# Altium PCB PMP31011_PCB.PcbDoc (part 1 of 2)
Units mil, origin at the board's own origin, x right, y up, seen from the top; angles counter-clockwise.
Board outline 3287.4 x 3750 mil, 4 copper layers (Top Layer, GND, Signal Layer, Bottom Layer), stack 84.834 mil thick; 100 components, 44 nets, 235 pads, 404 vias.
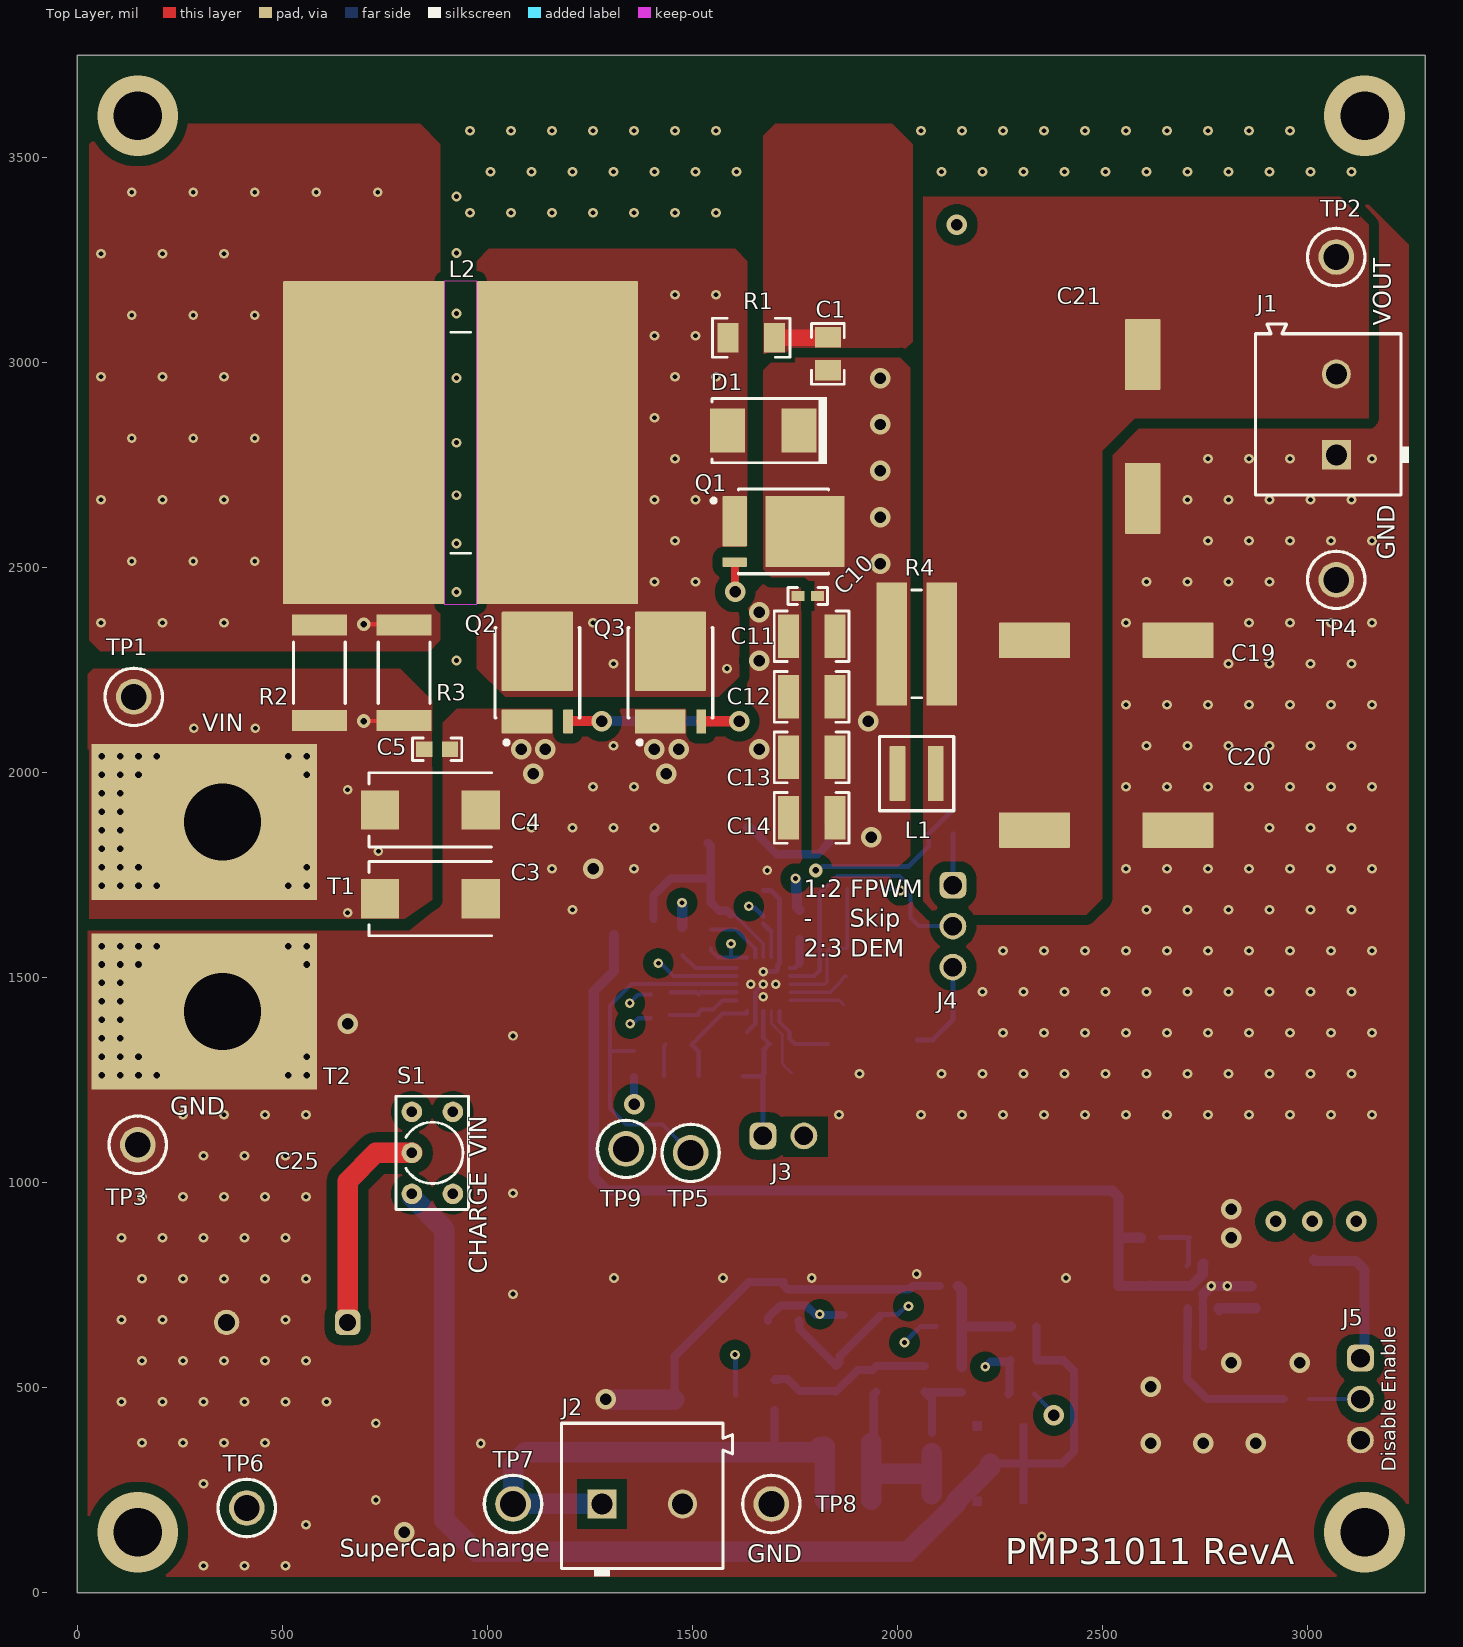
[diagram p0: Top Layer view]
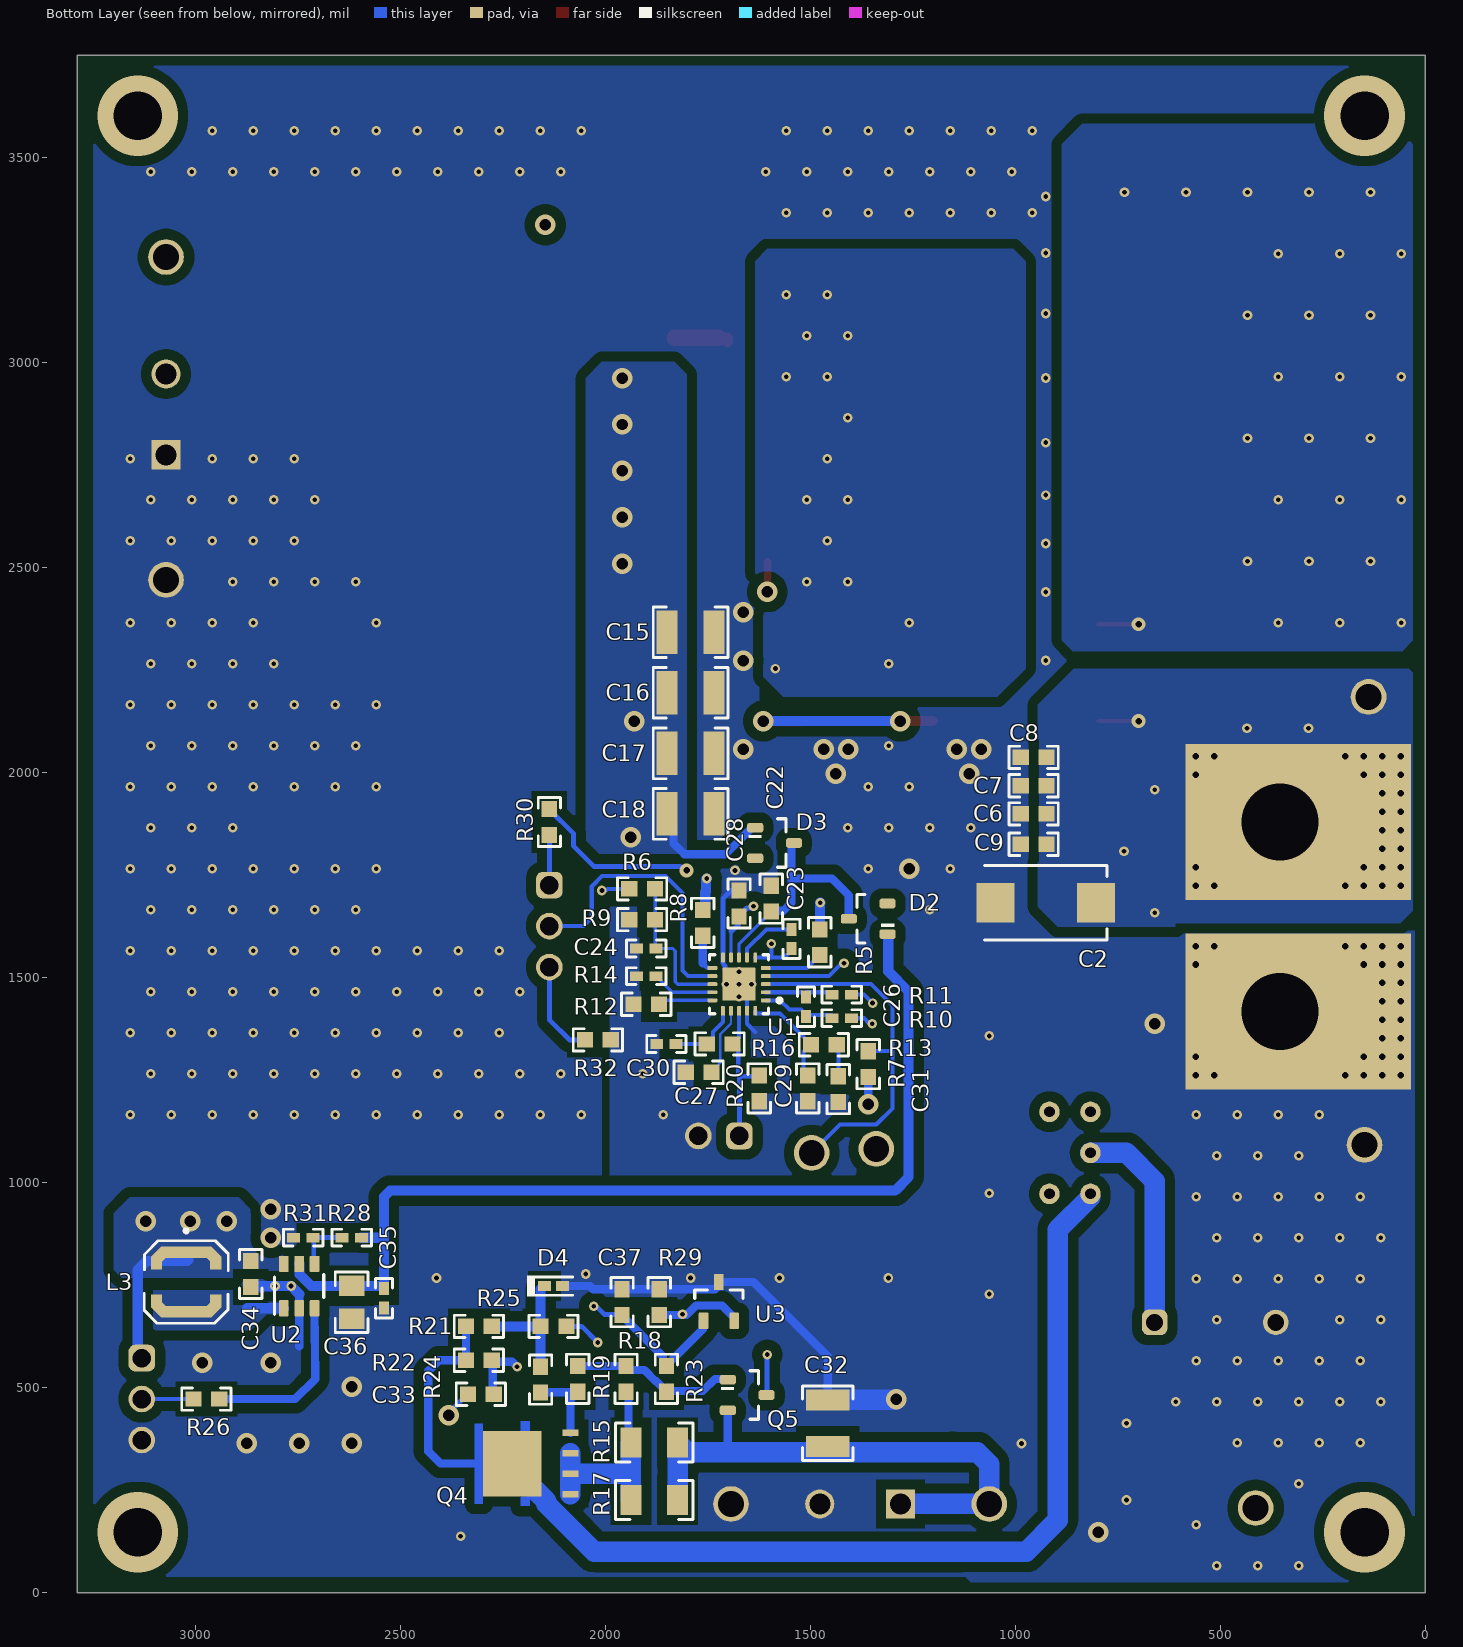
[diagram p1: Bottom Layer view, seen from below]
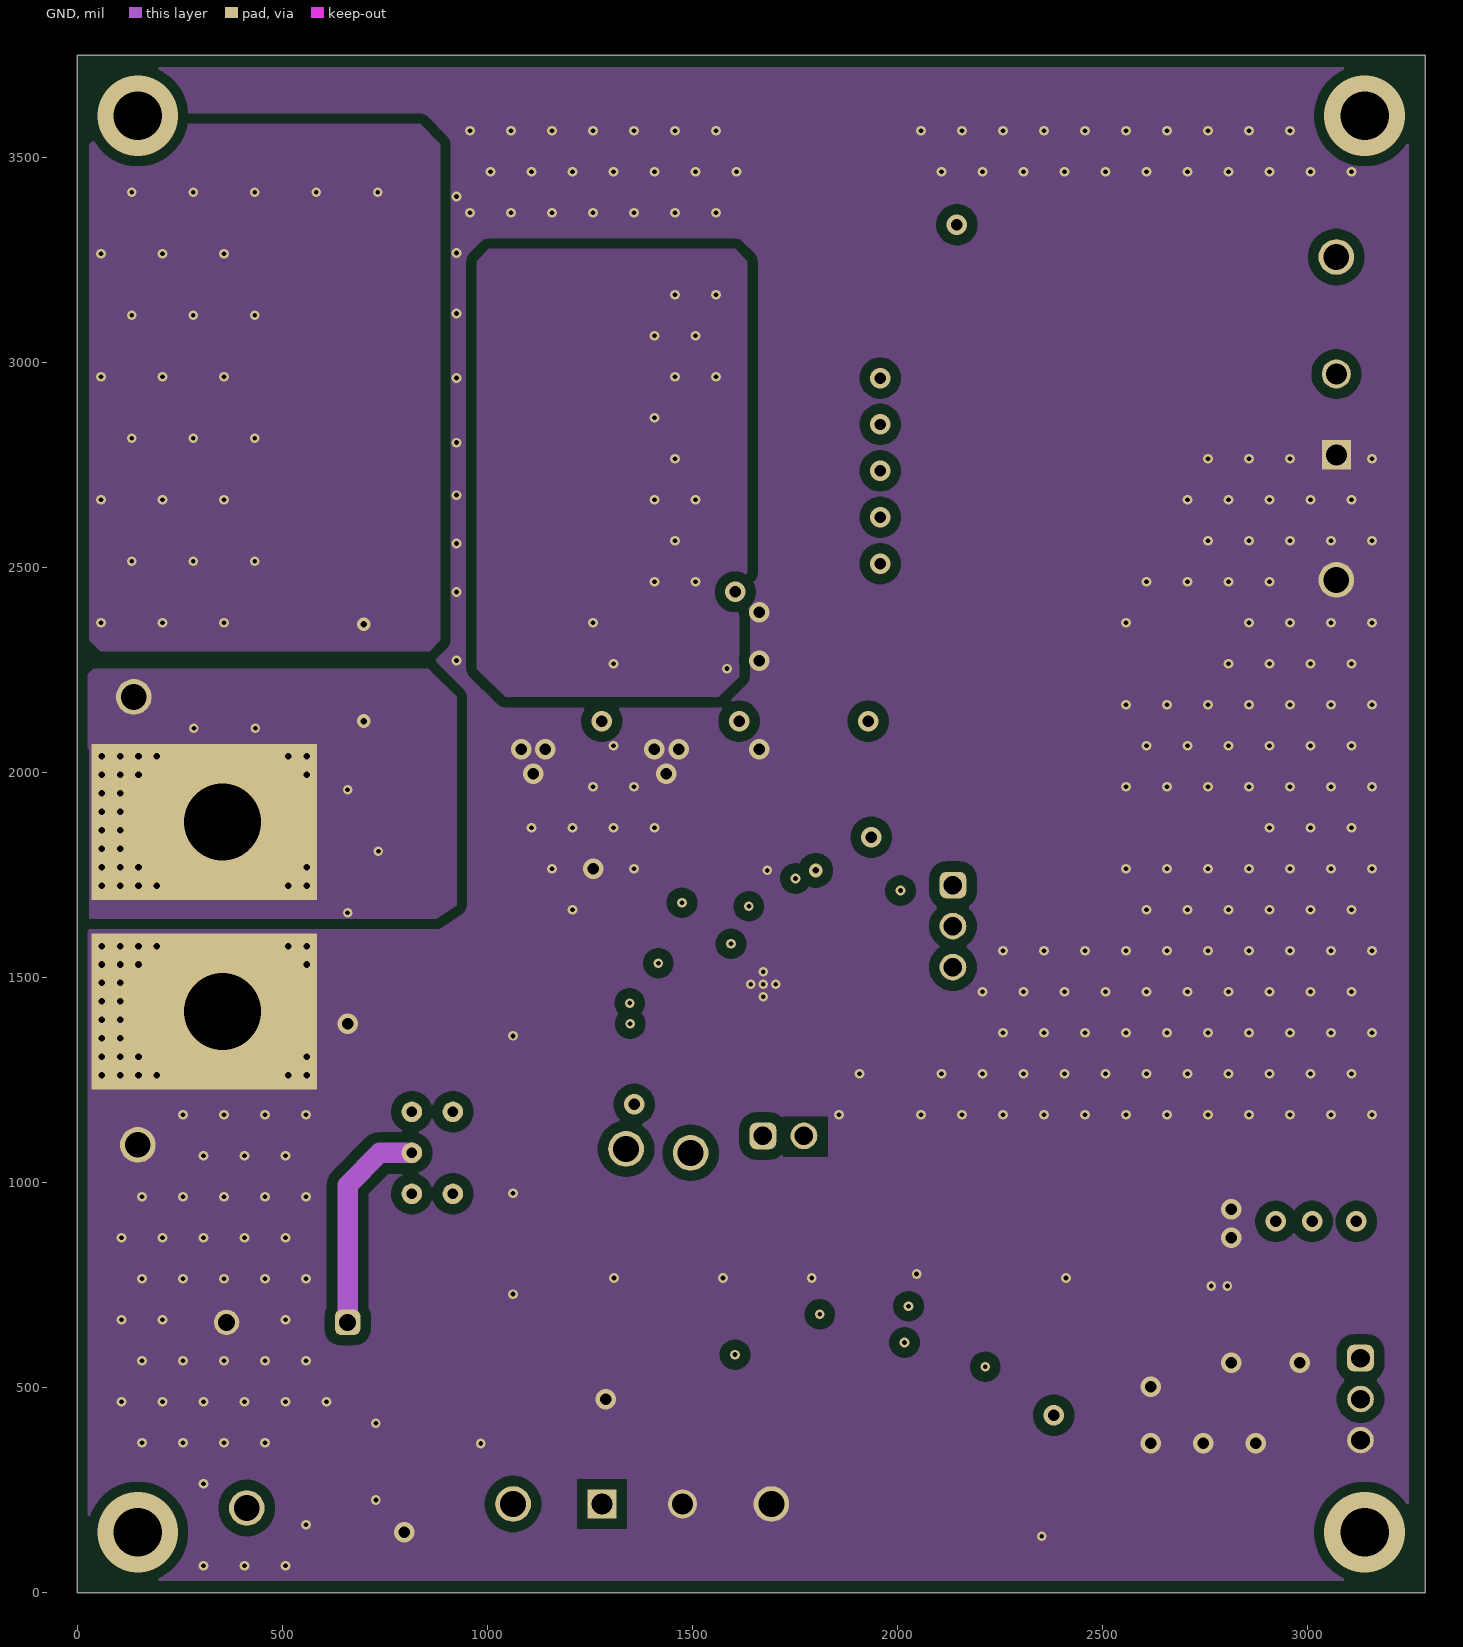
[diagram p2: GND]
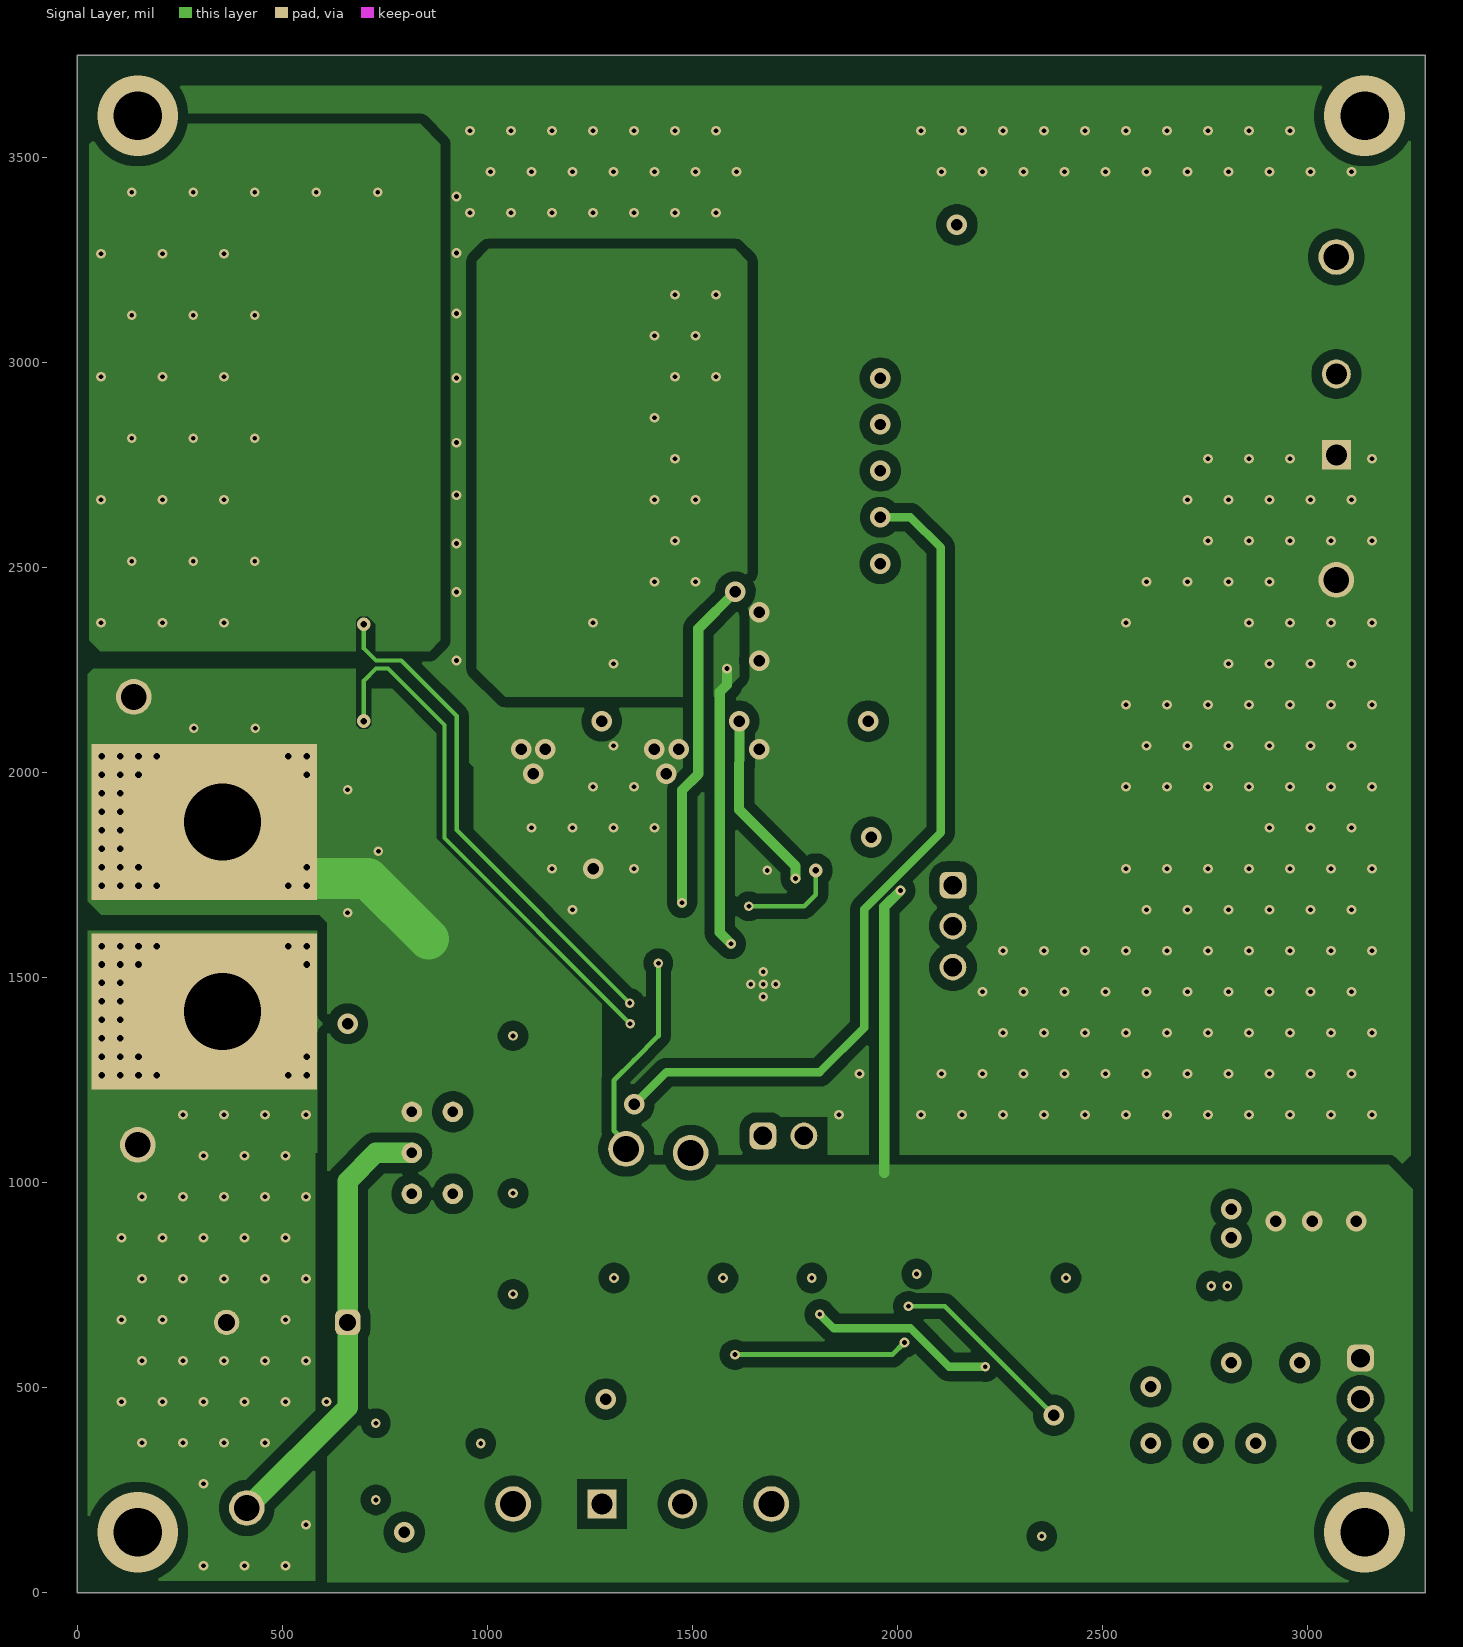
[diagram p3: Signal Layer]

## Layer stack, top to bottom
Top Solder: solder mask 0.4, Solder Resist, Dk 3.5
Top Layer: signal copper 1.4
Dielectric 2: dielectric 10, Dk 4.2
GND: signal copper 1.417
Dielectric1: core 59.2, FR-4, Dk 4.8
Signal Layer: signal copper 1.417
Dielectric 3: dielectric 10, Dk 4.2
Bottom Layer: signal copper 1.4
Bottom Solder: solder mask 0.4, Solder Resist, Dk 3.5

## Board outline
0,0 3287.4,0 3287.4,3750 0,3750

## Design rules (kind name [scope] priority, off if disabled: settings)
AcuteAngle [All] p1: minimum=4.50000000000000E+0001 checktracksonly=FALSE
AssemblyTestPointUsage [All] p1: valid=2
BoardOutlineClearance BoardOutlineClearance_MountingHoles [OnCopper and InComponentClass('Mounting Holes')] p1: gap=39.37 ignorepadtopadclearanceinfootprint=FALSE
BoardOutlineClearance BoardOutlineClearance_Poly [OnCopper and IsPoly] p2: gap=25 ignorepadtopadclearanceinfootprint=FALSE
BoardOutlineClearance [OnCopper and Not InComponentClass('Logo') and not InComponentClass('FiducialMark') and not InRegion(1000,500,4000,800) and not InPoly] p3: gap=75 ignorepadtopadclearanceinfootprint=FALSE
Clearance Clearance_Keepouts [((IsTrack Or IsArc) And Not InPoly) And IsFree and IsKeepOut vs ((IsTrack Or IsArc) And Not InPoly) And IsFree and IsKeepOut] p1: gap=0 ignorepadtopadclearanceinfootprint=FALSE
Clearance Clearance_Poly [InPolygon] p2: gap=25 ignorepadtopadclearanceinfootprint=TRUE
Clearance Clearance_FiducialMark [IsKeepOut and InComponentClass('FiducialMark') vs IsPad and InComponentClass('FiducialMark')] p3: gap=0 ignorepadtopadclearanceinfootprint=FALSE
Clearance [All] p4: gap=7.87 ignorepadtopadclearanceinfootprint=TRUE
ComponentClearance ComponentClearance_MountingHoles_FiducialMarks [InComponentClass('Mounting Holes') vs InComponentClass('FiducialMark')] p1: gap=50 collisioncheckmode=3 verticalgap=10 showdistances=FALSE
ComponentClearance ComponentClearance_Shunt [InComponentClass('Header') vs InComponentClass('Shunt')] p2: gap=0 collisioncheckmode=3 verticalgap=0 showdistances=FALSE
ComponentClearance ComponentClearance_Logo [InComponentClass('Logo')] p3: gap=50 collisioncheckmode=3 verticalgap=10 showdistances=FALSE
ComponentClearance ComponentClearance_ScrewToNut [(HasFootprint('NY PMS 440 0025 PH')) vs (HasFootprint('Keystone_1902C'))] p4: gap=5 collisioncheckmode=3 verticalgap=10 showdistances=FALSE
ComponentClearance ComponentClearance_MountingHoles [InComponentClass('Mounting Holes')] p5: gap=250 collisioncheckmode=3 verticalgap=100000 showdistances=FALSE
ComponentClearance ComponentClearance_SmallPassives [HasFootprint('0201*') or HasFootprint('0402*') or HasFootprint('0508') or HasFootprint('0603*') or HasFootprint('0612') or HasFootprint('0805*') or HasFootprint('0815*') or HasFootprint('0830*') or HasFootprint('1206*') or HasFootprint('1210*') or HasFootprint('1808*') or HasFootprint('1812*') or HasFootprint('1825*') or HasFootprint('2010*') or HasFootprint('2220*') or HasFootprint('2225*') or HasFootprint('2512*') or HasFootprint('2728*') or HasFootprint('3518*') vs HasFootprint('0201*') or HasFootprint('0402*') or HasFootprint('0508') or HasFootprint('0603*') or HasFootprint('0612') or HasFootprint('0805*') or HasFootprint('0815*') or HasFootprint('0830*') or HasFootprint('1206*') or HasFootprint('1210*') or HasFootprint('1808*') or HasFootprint('1812*') or HasFootprint('1825*') or HasFootprint('2010*') or HasFootprint('2220*') or HasFootprint('2225*') or HasFootprint('2512*') or HasFootprint('2728*') or HasFootprint('3518*')] p6: gap=14.96 collisioncheckmode=3 verticalgap=10 showdistances=FALSE
ComponentClearance ComponentClearance_THtoSMT [IsThruComponent vs IsSMTComponent] p7: gap=40 collisioncheckmode=3 verticalgap=30 showdistances=FALSE
ComponentClearance ComponentClearance_THtoTH [IsThruComponent vs IsThruComponent] p8: gap=30 collisioncheckmode=3 verticalgap=30 showdistances=FALSE
ComponentClearance [All] p9: gap=30 collisioncheckmode=3 verticalgap=10 showdistances=FALSE
DiffPairsRouting [All] p1: maxlimit=100 minlimit=10 mostfreqgap=10 toplayer_minwidth=15 toplayer_maxwidth=15 toplayer_prefwidth=15 midlayer1_minwidth=15 midlayer1_maxwidth=15 midlayer1_prefwidth=15 midlayer2_minwidth=15 midlayer2_maxwidth=15 midlayer2_prefwidth=15 bottomlayer_minwidth=15 bottomlayer_maxwidth=15 bottomlayer_prefwidth=15 maxuncoupledlength=1000
FabricationTestPointUsage TestPointUsage [All] p1: valid=2 allowmultiple=FALSE
FabricationTestpoint Testpoint [All] p1: side=3 testpointundercomponent=TRUE minsize=40 maxsize=100 preferedsize=60 minholesize=0 maxholesize=40 preferedholesize=32 testpointgrid=1 allowsidetop=TRUE allowsidebottom=TRUE usegrid=TRUE gridtolerance=0.01
FanoutControl Fanout_LCC [IsLCC] p1: bgadir=Out bgaviamode=Centered fanoutstyle=Auto fanoutdirection=Alternating viagrid=1 // Fanout_LCC (Default Rule)
FanoutControl Fanout_BGA [IsBGA] p2: bgadir=Out bgaviamode=Centered fanoutstyle=Auto fanoutdirection=Alternating viagrid=1 // Fanout_BGA (Default Rule)
FanoutControl Fanout_Default [All] p4: bgadir=Out bgaviamode=Centered fanoutstyle=Auto fanoutdirection=Alternating viagrid=1 // Fanout_Default (Default Rule)
FanoutControl Fanout_Small [(CompPinCount < 5)] p5: bgadir=Out bgaviamode=Centered fanoutstyle=Auto fanoutdirection=OutThenIn viagrid=1 // Fanout_Small (Default Rule)
HoleSize [All] p1: absolutevalues=TRUE maxlimit=251 minlimit=7.87 maxpercent=80.000 minpercent=20.000
MinimumAnnularRing MinimumAnnularRing_ThermalPadVias [IsVia and InAnyComponent] p1: minimumring=5.91
MinimumAnnularRing [All] p2: minimumring=5.91
MinimumSolderMaskSliver MinimumSolderMaskSliver_Logo [InComponentClass('Logo') vs InComponentClass('Logo')] p1: minsoldermaskwidth=0.7
MinimumSolderMaskSliver [All] p2: minsoldermaskwidth=3.94
PlaneConnect [All] p1: planeconnectstyle=Direct reliefexpansion=10 reliefentries=4 reliefconductorwidth=10 reliefairgap=10
PolygonConnect PolygonConnect_1 [All vs IsNamedPolygon('TOP_LAYER_NETD1_1_P000')] p1: connectstyle=Direct reliefconductorwidth=10 reliefentries=4 polygonreliefangle="90 Angle" airgapwidth=10
PolygonConnect [All] p2: connectstyle=Direct reliefconductorwidth=10 reliefentries=4 polygonreliefangle="90 Angle" airgapwidth=10
RoutingVias ThermalPadVias [IsVia and InAnyComponent] p1: holewidth=7.87 width=19.68 viastyle="Through Hole" minholewidth=7.87 minwidth=19.68 maxholewidth=12.99 maxwidth=23.62
RoutingVias [All] p2: holewidth=16 width=34 viastyle="Through Hole" minholewidth=11.81 minwidth=23.62 maxholewidth=40 maxwidth=65
SilkToBoardRegionClearance [Not ((IsComment or IsDesignator) And (Hide <> 'False')) and not InRegion(1000,500,4000,800)] p1:
SilkToSilkClearance SilkToSilkClearance_Pb-FreeLogo [(HasFootprint('Pb-Free_Overlay_Medium') OR HasFootprint('Pb-Free_Overlay_Small')) vs (HasFootprint('Pb-Free_Overlay_Medium') OR HasFootprint('Pb-Free_Overlay_Small'))] p1: silktosilkclearance=0
SilkToSilkClearance [All] p2: silktosilkclearance=3.94
SilkToSolderMaskClearance SilkToComponentPadClearance [(IsPad or IsFill or IsRegion) and InAnycomponent] p1: minsilkscreentomaskgap=5 clearancetoexposedcopper=TRUE
SilkToSolderMaskClearance "Silk to Solder Mask Opening" [All] p2: minsilkscreentomaskgap=3.94 clearancetoexposedcopper=FALSE
SolderMaskExpansion [All] p1: expansion=1.97 istentingtop=FALSE
UnRoutedNet [All] p1: checkbadconnections=TRUE
Width [All] p1: maxlimit=100 minlimit=6 preferedwidth=10 checkconnectedcopper=TRUE
14 further rules are at their usual default settings.

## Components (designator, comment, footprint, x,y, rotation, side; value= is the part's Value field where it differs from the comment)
C1 "GRM21BR72A153MA01L" 0805_HV 1830.71,3021.65 r90 top value=0.015uF
C2 "EEFSX0G221ER" 7343-20 925.2,1683.07 r0 bottom value=220uF
C3 "EEFSX0G221ER" 7343-20 861.02,1692.91 r0 top value=220uF
C4 "EEFSX0G221ER" 7343-20 861.02,1909.45 r0 top value=220uF
C5 "GRM188Z71A106MA73D" 0603 877.95,2057.09 r0 top value=10uF
C6 "GRM188Z71A106MA73D" 0603 954.72,1899.61 r0 bottom value=10uF
C7 "GRM188Z71A106MA73D" 0603 954.72,1968.5 r0 bottom value=10uF
C8 "GRM188Z71A106MA73D" 0603 954.72,2037.4 r0 bottom value=10uF
C9 "GRM188Z71A106MA73D" 0603 954.72,1825.79 r0 bottom value=10uF
C10 "GRM155R71C104JA88D" 0402 1781.5,2431.1 r180 top value=0.1uF
C11 "GRM32ER71E226KE15L" 1210_270 1791.34,2332.68 r180 top value=22uF
C12 "GRM32ER71E226KE15L" 1210_270 1791.34,2185.04 r180 top value=22uF
C13 "GRM32ER71E226KE15L" 1210_270 1791.34,2037.4 r180 top value=22uF
C14 "GRM32ER71E226KE15L" 1210_270 1791.34,1889.76 r180 top value=22uF
C15 "GRM32ER71E226KE15L" 1210_270 1791.34,2342.52 r180 bottom value=22uF
C16 "GRM32ER71E226KE15L" 1210_270 1791.34,2194.88 r180 bottom value=22uF
C17 "GRM32ER71E226KE15L" 1210_270 1791.34,2047.24 r180 bottom value=22uF
C18 "GRM32ER71E226KE15L" 1210_270 1791.34,1899.61 r180 bottom value=22uF
C19 "HHXB160ARA471MJA0G" FP-HHXB160ARA471MJA0G_RADIAL-MFG 2509.84,2322.83 r180 top
C20 "HHXB160ARA471MJA0G" FP-HHXB160ARA471MJA0G_RADIAL-MFG 2509.84,1860.24 r180 top
C21 "HHXB160ARA471MJA0G" FP-HHXB160ARA471MJA0G_RADIAL-MFG 2598.43,2844.49 r90 top
C22 "GRM188R71E105KA12D" 0603 1594.49,1692.91 r90 bottom value=1uF
C23 "GRM155R71H104ME14D" 0402 1545.28,1594.54 r270 bottom value=0.1uF
C24 "GRM1555C1H101JA01D" 0402 1899.61,1571.35 r0 bottom value=100pF
C25 "JUMT1226MHD" JUM_1600x3150 511.81,659.45 r180 top value=22000000uF
C26 "GRM155R71H221KA01D" 0402 1509.84,1429.51 r90 bottom value=220pF
C27 "GRM188R71C104KA01D" 0603 1771.65,1269.68 r0 bottom value=0.1uF
C28 "GRM188Z71C475KE21D" 0603 1673.23,1681.16 r90 bottom value=4.7uF
C29 "GRM188R71H682KA01D" 0603 1505.91,1230.32 r270 bottom value=6800pF
C30 "GRM1555C1H471JA01D" 0402 1850.39,1338.58 r0 bottom value=470pF
C31 "GRM188R71A684KA61D" 0603 1431.1,1228.4 r270 bottom value=0.68uF
C32 "GRM32ER71H475KA88L" 1210_270 1456.69,413.39 r90 bottom value=4.7uF
C33 "GRM188R72A102KA01D" 0603 2303.15,484.25 r180 bottom value=1000pF
C34 "GRM188Z71A106MA73D" 0603 2864.17,777.56 r270 bottom value=10uF
C35 "GRM155R71A104KA01D" 0402 2539.37,718.5 r270 bottom value=0.1uF
C36 "GRM21BZ71E106KE15L" 0805_HV 2618.11,708.66 r270 bottom value=10uF
C37 "GRM188R72A102KA01D" 0603 1958.66,708.66 r90 bottom value=1000pF
D1 "MBRS130LT3G" SMB 1673.23,2834.65 r180 top value=30V
D2 "BAS16LT1G" SOT-23 1358.27,1643.7 r0 bottom value=100V
D3 "BAS16LT1G" SOT-23 1586.61,1828.74 r180 bottom value=100V
D4 "DNP" SOD-523 2125.98,748.03 r180 bottom value=2.7V
J1 "691 101 710 002" Wurth_691101710002 3070.87,2874.02 r90 top
J2 "691 101 710 002" Wurth_691101710002 1377.95,216.54 r0 top
J3 "61300211121" WURTH_61300211121 1722.44,1114.17 r0 top
J4 "61300311121" WURTH_61300311121 2135.83,1625.98 r270 top
J5 "61300311121" WURTH_61300311121 3129.92,472.44 r270 top
L1 "XEL4014-221MEB" XEL4014 2047.24,1998.03 r0 top value=220nH
L2 "ETQP8MR33JFA" FP-ETQP8MR33JFA_SMT_INDUCTOR_12MM6_13MM2-MFG 935.04,2805.12 r0 top
L3 "LPS4018-103MRB" LPS4018 3021.65,757.87 r270 bottom value=10uH
Q1 "IAUC120N04S6L012ATMA1" FP-IAUC120N04S6N009ATMA1_TDSON8-MFG 1722.44,2588.58 r270 top
Q2 "IAUC120N04S6N006ATMA1" FP-IAUC120N04S6N009ATMA1_TDSON8-MFG 1122.05,2244.09 r0 top
Q3 "IAUC120N04S6N006ATMA1" FP-IAUC120N04S6N009ATMA1_TDSON8-MFG 1446.85,2244.09 r0 top
Q4 "SQJ415EP-T1_GE3" PowerPAK_SO-8L 2194.88,314.96 r0 bottom value=-60V
Q5 "MMBT2907ALT1G" SOT-23 1653.54,482.28 r180 bottom value="60 V"
R1 "CSR1206FTR820" 1206 1643.7,3061.02 r0 top value=0.82
R2 "ERJ-M1WTF1M0U" 2512 590.55,2244.09 r270 top value=0.001
R3 "ERJ-M1WTF1M0U" 2512 797.24,2244.09 r270 top value=0.001
R4 "RCL12250000Z0EG" 2512_WIDE_VISHAY 2047.24,2313.94 r0 top value=0
R5 "CRCW06031R00FKEA" 0603 1476.38,1586.61 r90 bottom value=1.00
R6 "CRCW060310K0FKEA" 0603 1909.45,1716.75 r0 bottom value=10.0k
R7 "CRCW06030000Z0EA" 0603 1358.27,1289.37 r270 bottom value=0
R8 "CRCW06031R00FKEA" 0603 1761.81,1633.86 r270 bottom value=1.00
R9 "CRCW06030000Z0EA" 0603 1909.45,1641.79 r180 bottom value=0
R10 "CRCW04020000Z0ED" 0402 1422.67,1401.29 r180 bottom value=0
R11 "CRCW040249R9FKED" 0402 1422.67,1458.71 r180 bottom value=49.9
R12 "CRCW0603110KFKEA" 0603 1899.61,1435.09 r180 bottom value=110k
R13 "CRCW06032K87FKEA" 0603 1466.34,1336.67 r0 bottom value=2.87k
R14 "CRCW04020000Z0ED" 0402 1899.61,1503.99 r180 bottom value=0
R15 "CRCW120610R0FKEA" 1206 1879.92,366.14 r0 bottom value=10.0
R16 "CRCW060349K9FKEA" 0603 1720.47,1338.58 r0 bottom value=49.9k
R17 "CRCW120610R0FKEA" 1206 1879.92,226.38 r0 bottom value=10.0
R18 "CRCW0603200RFKEA" 0603 1948.82,521.65 r270 bottom value=200
R19 "CRCW06030000Z0EA" 0603 2066.93,521.65 r270 bottom value=0
R20 "CRCW060333K2FKEA" 0603 1624.02,1230.32 r90 bottom value=33.2k
R21 "CRCW060310K0FKEA" 0603 2308.07,649.61 r0 bottom value=10.0k
R22 "CRCW0603200RFKEA" 0603 2308.07,566.93 r0 bottom value=200
R23 "CRCW06032K00FKEA" 0603 1850.39,521.65 r270 bottom value=2.00k
R24 "CRCW0603100RFKEA" 0603 2157.48,519.69 r270 bottom value=100
R25 "CRCW06030000Z0EA" 0603 2125.98,649.61 r0 bottom value=0
R26 "CRCW0603100KJNEA" 0603 2972.44,472.44 r0 bottom value=100k
R28 "CRCW040290K9FKED" 0402 2618.11,866.14 r180 bottom value=90.9k
R29 "CRCW060310K0FKEA" 0603 1868.11,708.66 r270 bottom value=10.0k
R30 "CRCW06030000Z0EA" 0603 2135.83,1879.92 r90 bottom value=0
R31 "CRCW040210K0FKED" 0402 2736.22,866.14 r180 bottom value=10.0k
R32 "CRCW06030000Z0EA" 0603 2017.72,1348.43 r0 bottom value=0
S1 "G13AP" SW_G1xAP 866.14,1072.83 r270 top
T1 "CB35-36-CY" CB35-36-CY 354.33,1879.92 r0 top
T2 "CB35-36-CY" CB35-36-CY 354.33,1417.32 r0 top
TP1 "5010" Keystone5010 137.8,2185.04 r0 top
TP2 "5010" Keystone5010 3070.87,3257.87 r0 top
TP3 "5011" Keystone5011 147.64,1092.52 r0 top
TP4 "5011" Keystone5011 3070.87,2470.47 r0 top
TP5 "5014" Keystone5014 1496.06,1072.83 r180 top
TP6 "5010" Keystone5010 413.39,206.69 r0 top
TP7 "5010" Keystone5010 1062.99,216.54 r0 top
TP8 "5011" Keystone5011 1692.91,216.54 r0 top
TP9 "5014" Keystone5014 1338.58,1082.68 r0 top
U1 "LM51521QRGRRQ1" RGR0020C-MFG 1673.23,1484.31 r0 bottom
U2 "TPS61071TDDCRQ1" DDC0006A_N 2746.06,748.03 r90 bottom
U3 "TL431AQDBZRQ1" DBZ0003A_N 1722.44,710.63 r90 bottom

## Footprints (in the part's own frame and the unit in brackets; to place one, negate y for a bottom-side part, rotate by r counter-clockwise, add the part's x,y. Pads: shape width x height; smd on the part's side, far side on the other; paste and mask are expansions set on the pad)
0402 [mm] "0402 from SM-752 data"
  rect 0.8x0.6 smd: 1(-0.6,0) 2(0.6,0)
  silkscreen extent -1.22,-0.52 1.22,0.52, body extent -0.55,-0.3 0.55,0.3, height 0.6
0603 [mm] "0603 from SM-752 data"
  rect 1x0.95 smd: 1(-0.8,0) 2(0.8,0)
  silkscreen extent -1.52,-0.69 1.52,0.69, body extent -0.87,-0.47 0.87,0.47, height 1
0805_HV [mil] "0805 with 30mil clearance between pads"
  rect 50x63 smd: 1(-40,0) 2(40,0)
  silkscreen extent -74,-40 74,40, body extent -43,-29 43,29, height 57
1206 [mm] "1206 from SM-752 data"
  rect 1.3x1.85 smd: 1(-1.45,0) 2(1.45,0)
  silkscreen extent -2.4,-1.21 2.4,1.21, body extent -1.7,-0.9 1.7,0.9, height 1.35
1210_270 [mm] "1210"
  rect 1.3x2.7 smd: 1(-1.45,0) 2(1.45,0)
  silkscreen extent -2.32,-1.57 2.32,1.57, body extent -1.7,-1.35 1.7,1.35, height 2.7
2512 [mm] "Chip Resistor, Body 6.3x3.2mm, IPC Medium Density"
  rect 1.3x3.4 smd: 1(-2.95,0) 2(2.95,0)
  silkscreen extent -1.9,-1.6 1.9,1.6, body extent -3.22,-1.67 3.22,1.67, height 0.71
2512_WIDE_VISHAY [mm] "Vishay recommended land pattern"
  rect 1.9x7.6 smd: 1(-1.55,0) 2(1.55,0)
  silkscreen extent -0.3,-3.32 0.3,3.35, body extent -1.7,-3.25 1.7,3.25, height 0.9
7343-20 [mm] "Medium density IPC, based on Kemet case V from T495 datasheet"
  rect 2.37x2.43 smd: 1(-3.12,0) 2(3.12,0)
  silkscreen extent -3.8,-2.3 3.8,2.3, body extent -3.8,-2.3 3.8,2.3, height 2
CB35-36-CY [mil] "Terminal 50A Lug"
  rect 550x380 hole 188 copper offset -45,0 paste-190: 1(0,0)
  body extent -960,-189 230,191, height 614
DBZ0003A_N [mm] "SOT23, 3-Leads, Body 2.9x1.3mm, Pitch 0.95mm, Lead Span 2.4mm, IPC Medium Density"
  rrect17% 1x0.6 smd: 1(-1.2,0.95) 2(-1.2,-0.95) 3(1.2,0)
  silkscreen extent 0.2,-1.5 0.7,1.5, body extent -1.26,-1.46 1.26,1.46, height 0.98
DDC0006A_N [mm]
  rrect17% 1x0.6 smd: 1(-1.375,0.95) 2(-1.375,0) 3(-1.375,-0.95) 4(1.375,-0.95) 5(1.375,0) 6(1.375,0.95)
  silkscreen extent -1.75,-1.52 0.7,1.53, body extent -1.43,-1.48 1.43,1.49, height 0.92
FP-ETQP8MR33JFA_SMT_INDUCTOR_12MM6_13MM2-MFG [mm]
  rrect1% 10x20 smd paste-1000 mask-1000: 1(-6,0) 2(6,0)
  Top Layer keep-out region: -1,-10 1,-10 1,10 -1,10
  silkscreen extent -0.63,-6.85 0.63,6.85, body extent -11.1,-10.1 11.1,10.1, height 0.25
FP-HHXB160ARA471MJA0G_RADIAL-MFG [mm]
  rrect5% 4.4x2.2 smd paste+0 mask+0: 1(-4.45,0) 2(4.45,0)
  body extent -6.9,-5.5 6.9,5.5, height 0.25
FP-IAUC120N04S6N009ATMA1_TDSON8-MFG [mm]
  rrect7% 3.14x1.5 smd paste-1000 mask-1000: 1-2-3(-0.635,-3.02)
  rrect17% 0.6x1.5 smd paste-1000 mask+0: 4(1.905,-3.02)
  rrect2% 4.41x4.9 smd paste-1000 mask-1000: 5-6-7-8(0,1.325)
  silkscreen extent -2.63,-4.45 2.63,2.79, body extent -2.96,-3.87 2.96,3.88, height 0.25
JUM_1600x3150 [mm] "TH, 2-Leads, Dia 16mm, Lead Spacing 7.5mm"
  rrect50% 1.575x1.575 hole 1.05: 1(-3.75,0)
  round 1.575 hole 1.05: 2(3.75,0)
  body extent -8.25,-8.25 8.25,8.25, height 33.5
Keystone5010 [mil] "Keystone Multipurpose loops"
  round 87 hole 63: 1(0,0)
  silkscreen extent -70,-70 70,70, body extent -63,-63 63,62, height 319
Keystone5011 [mil] "Keystone Multipurpose loops"
  round 87 hole 63: 1(0,0)
  silkscreen extent -70,-70 70,70, body extent -63,-63 63,62, height 319
Keystone5014 [mil] "Keystone Multipurpose loops"
  round 87 hole 63: 1(0,0)
  silkscreen extent -70,-70 70,70, body extent -63,-63 63,62, height 319
LPS4018 [mil]
  rect 28x123 smd: 1(-72.5,0) 2(72.5,0)
  rect 35.5x28 smd rot 135: 1(-64,-64) 2(64,64)
  rect 35.5x28 smd rot 45: 1(-64,64) 2(64.5,-63.5)
  rect 31.5x28 smd: 1(-46,-72.5) 1(-46,72.5) 2(46,-72.5) 2(46,72.5)
  silkscreen extent -129,-103 101,103, body extent -81,-81 81,81, height 71
PowerPAK_SO-8L [mm] "based on Vishay recommended land pattern Document 63818 Feb 7, 2012"
  rect 1x0.41 smd: 1(-2.805,1.905) 2(-2.805,0.635) 3(-2.805,-0.635) 4(-2.805,-1.905)
  rect 3.63x4.061 smd: 5(0.805,0)
  Top Layer region: -0.297,-2.03 0.298,-2.03 0.298,-2.64 -0.297,-2.64
  Top Layer region: -0.298,2.64 0.297,2.64 0.297,2.03 -0.298,2.03
  Top Layer region: 2.615,2.5 3.125,2.5 3.125,-2.5 2.615,-2.5
  body extent -3.07,-2.57 3.08,2.57, height 1.21
RGR0020C-MFG [mm]
  rrect42% 0.6x0.24 smd paste+0 mask+0: 1(-1.65,1) 2(-1.65,0.5) 3(-1.65,0) 4(-1.65,-0.5) 5(-1.65,-1) 11(1.65,-1) 12(1.65,-0.5) 13(1.65,0) 14(1.65,0.5) 15(1.65,1)
  rrect42% 0.24x0.6 smd paste+0 mask+0: 6(-1,-1.65) 7(-0.5,-1.65) 8(0,-1.65) 9(0.5,-1.65) 10(1,-1.65) 16(1,1.65) 17(0.5,1.65) 18(0,1.65) 19(-0.5,1.65) 20(-1,1.65)
  rrect5% 2.05x2.05 smd paste-1000 mask+0: 21(0,0)
  silkscreen extent -2.62,-1.83 1.83,1.83, body extent -1.75,-1.75 1.75,1.75, height 1
SMB [mil] "Molded Diode, 2-Leads, Body 5.4x3.6mm, IPC Medium Density, based on OnSemi component dimensions"
  rect 85x107.99 smd: 1(-87.01,0) 2(87.01,0)
  silkscreen extent -155,-82 125,82, body extent -106,-71 106,71, height 91
SOD-523 [mm] "NXP Semiconductor recommended land pattern, nominal STEP model"
  rect 0.8x0.6 smd paste-0.05: 1(-0.55,0) 2(0.55,0)
  silkscreen extent -1.65,-0.66 1.2,0.66, body extent -0.8,-0.4 0.8,0.4, height 0.72
SOT-23 [mm] "SOT23, 3-Leads, Body 2.9x1.3mm, Pitch 0.95mm, Lead Span 2.5mm, IPC Medium Density"
  rrect50% 1x0.6 smd: 1(-1.2,0.95) 2(-1.2,-0.95) 3(1.2,0)
  silkscreen extent -1.62,-1.5 0.7,1.5, body extent -1.16,-1.45 1.21,1.45, height 1
SW_G1xAP [mil] "Switch, NKK G Series"
  round 50 hole 26: 1(-100,50) 3(100,50) 4(-100,-50) 5(0,-50) 6(100,-50)
  silkscreen extent -138,-88 138,89, body extent -138,-88 138,89, height 424
WURTH_61300211121 [mm] "Header, 2.54mm, 2x1, TH"
  rrect50% 1.65x1.65 hole 1.15: 1(-1.27,0)
  round 1.65 hole 1.15: 2(1.27,0)
  body extent -2.54,-1.27 2.54,1.27, height 8.54
WURTH_61300311121 [mm] "Header, 2.54mm, 3x1, TH"
  rrect50% 1.65x1.65 hole 1.15: 1(-2.54,0)
  round 1.65 hole 1.15: 2(0,0) 3(2.54,0)
  body extent -3.81,-1.27 3.81,1.27, height 8.54
Wurth_691101710002 [mm] "Terminal Block, 5 mm, 2x1, TH"
  rect 1.8x1.8 hole 1.3: 1(-2.5,0)
  round 1.8 hole 1.3: 2(2.5,0)
  silkscreen extent -5,-4.5 5.6,5, body extent -5.6,-4 5.6,5, height 12.5
XEL4014 [mm] "SMD, 2-Leads, Body 4x4mm, Pitch 2.37mm"
  rrect10% 0.98x3.4 smd: 1(-1.185,0) 2(1.185,0)
  silkscreen extent -2.3,-2.3 2.3,2.3, body extent -2.15,-2.15 2.15,2.15, height 1.4

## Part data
C1: library part CMP-0008366-2, "CAP, CERM, 0.015 uF, 100 V, +/- 20%, X7R, 0805", Cap_Case=0805, Manufacturer=MuRata, Supplier Part Number 1=490-1656-1-ND, TempCo=X7R, Tolerance_%=20%, Value1=Unknown, Value2=100V, ValueDisplayed=0.015uF
C2 C3 C4: library part CMP-0012259-4, "CAP, Aluminum Polymer, 220 uF, 4 V, +/- 20%, 9 ohm, 7343-20, SMD", Cap_Case=7343-20, Manufacturer=Panasonic, Supplier Part Number 1=PCE4991CT-ND, Tolerance_%=20%, Value1="9 ohm", Value2=4V, ValueDisplayed=220uF
C5 C6 C7 C8 C9 C34: library part CMP-0007497-5, "CAP, CERM, 10 uF, 10 V, +/- 20%, X7R, 0603", Cap_Case=0603, Manufacturer=MuRata, Supplier Part Number 1=81-GRM188Z71A106MA3D, TempCo=X7R, Tolerance_%=20%, Value1=Unknown, Value2=10V, ValueDisplayed=10uF
C10: library part CMP-0006640-2, "CAP, CERM, 0.1 uF, 16 V, +/- 5%, X7R, 0402", Cap_Case=0402, Manufacturer=MuRata, Supplier Part Number 1=490-6327-1-ND, TempCo=X7R, Tolerance_%=5%, Value1=Unknown, Value2=16V, ValueDisplayed=0.1uF
C11 C12 C13 C14 C15 C16 C17 C18: library part CMP-0009224-2, "CAP, CERM, 22 uF, 25 V, +/- 10%, X7R, 1210", Cap_Case=1210, Manufacturer=MuRata, Supplier Part Number 1=490-5313-1-ND, TempCo=X7R, Tolerance_%=10%, Value1=Unknown, Value2=25V, ValueDisplayed=22uF
C19 C20 C21: library part CMP-0086437-1, "Cap Aluminum Polymer 470uF 16VDC 20% (10 X 10mm) SMD 0.018 Ohm 2600mA 5000h 105C Automotive T/R", Manufacturer="United Chemi-Con", Tolerance_%=20%
C22: library part CMP-0007405-4, "CAP, CERM, 1 uF, 25 V, +/- 10%, X7R, 0603", Cap_Case=0603, Manufacturer=MuRata, Supplier Part Number 1=490-5307-1-ND, TempCo=X7R, Tolerance_%=10%, Value1=Unknown, Value2=25V, ValueDisplayed=1uF
C23: library part CMP-0006675-2, "CAP, CERM, 0.1 uF, 50 V, +/- 20%, X7R, 0402", Cap_Case=0402, Manufacturer=MuRata, Supplier Part Number 1=490-10701-1-ND, TempCo=X7R, Tolerance_%=20%, Value1=Unknown, Value2=50V, ValueDisplayed=0.1uF
C24: library part CMP-0006410-2, "CAP, CERM, 100 pF, 50 V, +/- 5%, C0G/NP0, 0402", Cap_Case=0402, Manufacturer=MuRata, Supplier Part Number 1=81-GRM1555C1H101JA1D, TempCo=C0G/NP0, Tolerance_%=5%, Value1=Unknown, Value2=50V, ValueDisplayed=100pF
C25: library part CMP-0084050-1, "CAP, Electric Double Layer, 22000000 µF, 2.7 V,+/- 20%, 0.07 ohm, TH", Cap_Case=16x31.5mm, Manufacturer=Nichicon, Tolerance_%=20%, Value1="0.07 ohm", Value2=2.7V, ValueDisplayed=22F
C26: library part CMP-0006682-2, "CAP, CERM, 220 pF, 50 V, +/- 10%, X7R, 0402", Cap_Case=0402, Manufacturer=MuRata, Supplier Part Number 1=490-1298-1-ND, TempCo=X7R, Tolerance_%=10%, Value1=Unknown, Value2=50V, ValueDisplayed=220pF
C27: library part CMP-0007378-5, "CAP, CERM, 0.1 uF, 16 V, +/- 10%, X7R, 0603", Cap_Case=0603, Manufacturer=MuRata, Supplier Part Number 1=490-1532-1-ND, TempCo=X7R, Tolerance_%=10%, Value1=Unknown, Value2=16V, ValueDisplayed=0.1uF
C28: library part CMP-0064936-4, "CAP, CERM, 4.7 uF, 16 V,+/- 10%, X7R, 0603", Cap_Case=0603, Manufacturer=MuRata, TempCo=X7R, Tolerance_%=10%, Value1=Unknown, Value2=16V, ValueDisplayed=4.7uF
C29: library part CMP-0007462-4, "CAP, CERM, 6800 pF, 50 V, +/- 10%, X7R, 0603", Cap_Case=0603, Manufacturer=MuRata, Supplier Part Number 1=490-1508-1-ND, TempCo=X7R, Tolerance_%=10%, Value1=Unknown, Value2=50V, ValueDisplayed=6800pF
C30: library part CMP-0006470-2, "CAP, CERM, 470 pF, 50 V, +/- 5%, C0G/NP0, 0402", Cap_Case=0402, Manufacturer=MuRata, Supplier Part Number 1=490-1297-1-ND, TempCo=C0G/NP0, Tolerance_%=5%, Value1=Unknown, Value2=50V, ValueDisplayed=470pF
C31: library part CMP-0007375-4, "CAP, CERM, 0.68 uF, 10 V, +/- 10%, X7R, 0603", Cap_Case=0603, Manufacturer=MuRata, Supplier Part Number 1=GRM188R71A684KA61D-ND, TempCo=X7R, Tolerance_%=10%, Value1=Unknown, Value2=10V, ValueDisplayed=0.68uF
C32: library part CMP-0009228-2, "CAP, CERM, 4.7 uF, 50 V, +/- 10%, X7R, 1210", Cap_Case=1210, Manufacturer=MuRata, Supplier Part Number 1=490-1864-1-ND, TempCo=X7R, Tolerance_%=10%, Value1="0.002 ohm", Value2=50V, ValueDisplayed=4.7uF
C33 C37: library part CMP-0007467-4, "CAP, CERM, 1000 pF, 100 V, +/- 10%, X7R, 0603", Cap_Case=0603, Manufacturer=MuRata, Supplier Part Number 1=490-1472-1-ND, TempCo=X7R, Tolerance_%=10%, Value1=Unknown, Value2=100V, ValueDisplayed=1000pF
C35: library part CMP-0006629-2, "CAP, CERM, 0.1 uF, 10 V, +/- 10%, X7R, 0402", Cap_Case=0402, Manufacturer=MuRata, Supplier Part Number 1=GRM155R71A104KA01D-ND, TempCo=X7R, Tolerance_%=10%, Value1=Unknown, Value2=10V, ValueDisplayed=0.1uF
C36: library part CMP-0008378-2, "CAP, CERM, 10 uF, 25 V, +/- 10%, X7R, 0805", Cap_Case=0805, Manufacturer=MuRata, Supplier Part Number 1=81-GRM21BZ71E106KE5L, TempCo=X7R, Tolerance_%=10%, Value1=Unknown, Value2=25V, ValueDisplayed=10uF
D1: library part CMP-0028527-2, "Diode, Schottky, 30 V, 1 A, SMB", Manufacturer="ON Semiconductor", Value1=1A, Value2=0.395V
D2 D3: library part CMP-0029193-2, "Diode, Switching, 100 V, 0.2 A, SOT-23", Manufacturer="ON Semiconductor", Value1=0.2A, Value2=1.25V
D4: library part CMP-0005892-4, "Diode, Zener, 2.7 V, 300 mW, SOD-523", Manufacturer="Diodes Inc.", PartNumber=BZT52C2V7T-7, Power_W=300mW, Value1=0.3W
J1 J2: library part CMP-0054828-1, "Terminal Block, 5 mm, 2x1, Tin, TH", Manufacturer="Wurth Elektronik", Supplier Part Number 1=732-2026-ND
J3: library part CMP-0054794-2, "Header, 2.54 mm, 2x1, Gold, TH", Color=Black, Manufacturer="Wurth Elektronik", Supplier Part Number 1=732-5315-ND
J4 J5: library part CMP-0054796-2, "Header, 2.54 mm, 3x1, Gold, TH", Color=Black, Manufacturer="Wurth Elektronik", Supplier Part Number 1=732-5316-ND
L1: library part CMP-0061070-1, "Inductor, Shielded, Composite, 220 nH, 12 A, 0.0075 ohm, AEC-Q200 Grade 1, SMD", Manufacturer=Coilcraft, Value1="0.0075 ohm", Value2=12A, ValueDisplayed=DNP
L2: library part CMP-0091958-2, "Power Inductor, Aec-Q200, Shld, 330Nh; Inductance: 330Nh; Rms Current (Irms): 44.4A; Inductor Construction: shielded;...", Manufacturer=Panasonic, Operating Temperature Range="-40°C to +160°C", Test Frequency=100kHz, Tolerance_%=20%
L3: library part CMP-0060471-1, "Inductor, Shielded Drum Core, Ferrite, 10 uH, 1.25 A, 0.18 ohm, SMD", Manufacturer=Coilcraft, Supplier Part Number 1=994-LPS4018-103MRB, Value1="0.18 ohm", Value2=1.25A, ValueDisplayed=10uH
Q1 Q2 Q3: library part CMP-0086959-1, "Trans Mosfet N-ch 40V 120A 8-PIN Pg-tdson T/R", Manufacturer=Infineon, PartNumber=IAUC120N04S6N010ATMA1
Q4: library part CMP-0083987-2, "MOSFET, P-CH, -40 V, -30 A, AEC-Q101, PowerPAK_SO-8L", Alternate Manufacturer=None, Manufacturer=Vishay-Semiconductor, Value1="0.024 ohm", Value2="73 nC"
Q5: library part CMP-0000344-2, "Transistor, PNP, 60 V, 0.6 A, SOT-23", Manufacturer="ON Semiconductor", Supplier Part Number 1=MMBT2907ALT1GOSCT-ND, Value1="0.6 A"
R1: library part CMP-0017275-2, "RES, 0.82, 1%, 0.5 W, 1206", Manufacturer="Stackpole Electronics Inc", Power_W=500mW, Supplier Part Number 1=CSR1206FTR820CT-ND, TempCo="100 ppm/C", Tolerance_%=1%, Value2=0.5W, Value_Code=R820, ValueDisplayed=`DNP
R2 R3: library part CMP-0015817-2, "RES, 0.001, 1%, 1 W, 2512", Manufacturer=Panasonic, Power_W=1W, Supplier Part Number 1=P1.0NDCT-ND, TempCo=ppm/C, Tolerance_%=1%, Value_Code=1L000, ValueDisplayed=0.001
R4: library part CMP-0015368-2, "RES, 0, 5%, 2 W, 2512 WIDE", Manufacturer="Vishay Draloric", Power_W=2W, Supplier Part Number 1=RCL0.0ECT-ND, TempCo=ppm/C, Tolerance_%=5%, Value_Code=0000, ValueDisplayed=0
R5 R8: library part CMP-0022170-4, "RES, 1.00, 1%, 0.1 W, AEC-Q200 Grade 0, 0603", Manufacturer=Vishay-Dale, Power_W=100mW, Supplier Part Number 1=52K8059, TempCo="100 ppm/C", Tolerance_%=1%, Value2=0.1W, Value_Code=1R00, ValueDisplayed=1.00
R6 R21 R29: library part CMP-0021998-4, "RES, 10.0 k, 1%, 0.1 W, AEC-Q200 Grade 0, 0603", Manufacturer=Vishay-Dale, Power_W=100mW, Supplier Part Number 1=541-10.0KHCT-ND, TempCo="100 ppm/C", Tolerance_%=1%, Value2=0.1W, Value_Code=10k0, ValueDisplayed=10.0k
R7 R19 R25 R30 R32: library part CMP-0025697-4, "RES, 0, 5%, 0.1 W, AEC-Q200 Grade 0, 0603", Manufacturer=Vishay-Dale, Power_W=100mW, Supplier Part Number 1=541-0.0GCT-ND, TempCo="200 ppm/C", Tolerance_%=5%, Value2=0.1W, Value_Code=0000, ValueDisplayed=0
R9: library part CMP-0025697-4, "RES, 0, 5%, 0.1 W, AEC-Q200 Grade 0, 0603", Manufacturer=Vishay-Dale, Power_W=100mW, Supplier Part Number 1=541-0.0GCT-ND, TempCo="200 ppm/C", Tolerance_%=5%, Value2=0.1W, Value_Code=0000, ValueDisplayed=DNP
R10 R14: library part CMP-0026822-3, "RES, 0, 5%, 0.063 W, AEC-Q200 Grade 0, 0402", Manufacturer=Vishay-Dale, Power_W=63mW, Supplier Part Number 1=541-0.0JCT-ND, TempCo="200 ppm/C", Tolerance_%=5%, Value2=0.063W, Value_Code=0000, ValueDisplayed=0
R11: library part CMP-0026404-2, "RES, 49.9, 1%, 0.063 W, AEC-Q200 Grade 0, 0402", Manufacturer=Vishay-Dale, Power_W=63mW, Supplier Part Number 1=541-49.9LCT-ND, TempCo="100 ppm/C", Tolerance_%=1%, Value2=0.063W, Value_Code=49R9, ValueDisplayed=49.9
R12: library part CMP-0022008-4, "RES, 110 k, 1%, 0.1 W, AEC-Q200 Grade 0, 0603", Manufacturer=Vishay-Dale, Power_W=100mW, Supplier Part Number 1=541-110KHCT-ND, TempCo="100 ppm/C", Tolerance_%=1%, Value2=0.1W, Value_Code=110k
R13: library part CMP-0022283-4, "RES, 2.87 k, 1%, 0.1 W, AEC-Q200 Grade 0, 0603", Manufacturer=Vishay-Dale, Power_W=100mW, Supplier Part Number 1=541-2.87KHCT-ND, TempCo="100 ppm/C", Tolerance_%=1%, Value2=0.1W, Value_Code=2k87, ValueDisplayed=2.87k
R15 R17: library part CMP-0016583-3, "RES, 10.0, 1%, 0.25 W, AEC-Q200 Grade 0, 1206", Manufacturer=Vishay-Dale, Power_W=250mW, Supplier Part Number 1=541-10.0FCT-ND, TempCo="100 ppm/C", Tolerance_%=1%, Value2=0.25W, Value_Code=10R0, ValueDisplayed=10.0
R16: library part CMP-0022447-4, "RES, 49.9 k, 1%, 0.1 W, AEC-Q200 Grade 0, 0603", Manufacturer=Vishay-Dale, Power_W=100mW, Supplier Part Number 1=541-49.9KHCT-ND, TempCo="100 ppm/C", Tolerance_%=1%, Value2=0.1W, Value_Code=49k9, ValueDisplayed=49.9k
R18 R22: library part CMP-0022201-5, "RES, 200, 1%, 0.1 W, AEC-Q200 Grade 0, 0603", Manufacturer=Vishay-Dale, Power_W=100mW, Supplier Part Number 1=541-200HCT-ND, TempCo="100 ppm/C", Tolerance_%=1%, Value2=0.1W, Value_Code=200R, ValueDisplayed=200
R20: library part CMP-0022339-4, "RES, 33.2 k, 1%, 0.1 W, AEC-Q200 Grade 0, 0603", Manufacturer=Vishay-Dale, Power_W=100mW, Supplier Part Number 1=541-33.2KHCT-ND, TempCo="100 ppm/C", Tolerance_%=1%, Value2=0.1W, Value_Code=33k2, ValueDisplayed=33.2k
R23: library part CMP-0022268-4, "RES, 2.00 k, 1%, 0.1 W, AEC-Q200 Grade 0, 0603", Manufacturer=Vishay-Dale, Power_W=100mW, Supplier Part Number 1=541-2.00KHCT-ND, TempCo="100 ppm/C", Tolerance_%=1%, Value2=0.1W, Value_Code=2k00, ValueDisplayed=2.00k
R24: library part CMP-0021991-4, "RES, 100, 1%, 0.1 W, AEC-Q200 Grade 0, 0603", Manufacturer=Vishay-Dale, Power_W=100mW, Supplier Part Number 1=541-100HCT-ND, TempCo="100 ppm/C", Tolerance_%=1%, Value2=0.1W, Value_Code=100R, ValueDisplayed=100
R26: library part CMP-0025698-4, "RES, 100 k, 5%, 0.1 W, AEC-Q200 Grade 0, 0603", Manufacturer=Vishay-Dale, Power_W=100mW, Supplier Part Number 1=541-100KGCT-ND, TempCo="200 ppm/C", Tolerance_%=5%, Value2=0.1W, Value_Code=100k
R28: library part CMP-0026605-2, "RES, 90.9 k, 1%, 0.063 W, AEC-Q200 Grade 0, 0402", Manufacturer=Vishay-Dale, Power_W=63mW, Supplier Part Number 1=541-90.9KLCT-ND, TempCo="100 ppm/C", Tolerance_%=1%, Value2=0.063W, Value_Code=90k9, ValueDisplayed=90.9k
R31: library part CMP-0025958-3, "RES, 10.0 k, 1%, 0.063 W, AEC-Q200 Grade 0, 0402", Manufacturer=Vishay-Dale, Power_W=63mW, Supplier Part Number 1=541-10.0KLCT-ND, TempCo="100 ppm/C", Tolerance_%=1%, Value2=0.063W, Value_Code=10k0, ValueDisplayed=10.0k
S1: library part CMP-0002118-3, "Switch, Toggle, SPDT 1Pos, TH", CurrentRating_mA=400A, Manufacturer="NKK Switches", Supplier Part Number 1=360-1769-ND
T1 T2: library part CMP-0055442-1, "Terminal 50A Lug", Manufacturer=Panduit, Supplier Part Number 1=CB35-36-CY-ND, Voltage_V=600V
TP1 TP2 TP6 TP7: library part CMP-0055147-1, "Test Point, Multipurpose, Red, TH", Color=Red, Manufacturer=Keystone, Supplier Part Number 1=36-5010-ND
TP3 TP4 TP8: library part CMP-0055148-1, "Test Point, Multipurpose, Black, TH", Color=Black, Manufacturer=Keystone, Supplier Part Number 1=36-5011-ND
TP5 TP9: library part CMP-0055151-1, "Test Point, Multipurpose, Yellow, TH", Color=Yellow, Manufacturer=Keystone, Supplier Part Number 1=36-5014-ND
U1: library part CMP-0088589-2, "Automotive Low-IQ Synchronous Boost Controller for Start-stop", Manufacturer="Texas Instruments", Max Supply Voltage=42V, Min Supply Voltage=3.8V, Nominal Supply Current=1.2mA, Operating Temperature Range="-40°C to +150°C", Output Voltage=5-20V, Switching Frequency=100-2200kHz
U2: library part CMP-0067186-2, "Automotive Catalog Adjustable, 600-mA Switch, 90% Efficient PWM Boost Converter, DDC0006A (SOT-23-T-6)", Alternate Manufacturer="Texas Instruments"
U3: library part CMP-0033164-1, "Automotive Catalog Adjustable Precision Shunt Regulator, 34 ppm / degC, 100 mA, -40 to 125 degC, 3-pin SOT-23 (DBZ), Green (RoHS & no Sb/Br)", Manufacturer="Texas Instruments", Rating=Automotive, Temp Coeff(Typ)(ppm/ degree C)=34

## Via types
v1: diameter 23.62, hole 11.81, Top Layer to Bottom Layer, 298 vias
v2: diameter 32, hole 16, Top Layer to Bottom Layer, 56 vias
v3: diameter 50, hole 28, Top Layer to Bottom Layer, 37 vias
v4: diameter 23.62, hole 11.81, Top Layer to Bottom Layer, tented both sides, 6 vias
v5: diameter 196.85, hole 118.11, Top Layer to Bottom Layer, 4 vias
v6: diameter 34, hole 16, Top Layer to Bottom Layer, 3 vias

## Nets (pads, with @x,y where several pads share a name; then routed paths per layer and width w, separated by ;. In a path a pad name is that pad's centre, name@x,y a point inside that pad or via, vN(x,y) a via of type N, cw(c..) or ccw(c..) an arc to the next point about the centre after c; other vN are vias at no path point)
AGND: C2.2 C3.2 C4.2 C5.2 C6.2 C7.2 C8.2 C9.2 C10.2 C11.2 C12.2 C13.2 C14.2 C15.2 C16.2 C17.2 C18.2 C19.1 C20.1 C21.1 C22.2 C24.2 C25.2 C27.2 C28.2 C29.2 C30.2 C31.2 C32.2 C34.2 C35.2 C36.2 C37.2 D4.2 J1.1 J2.2 J3.2 J5.3 Q2.1-2-3 Q3.1-2-3 R9.1 R12.1 R14.1 R20.1 R29.1 R31.1 R32.1 T2.1 TP3.1 TP4.1 TP8.1 U1.10 U1.19 U1.21 U2.2 U3.3 | length 1654.8
  Bottom Layer w10: 1633.86,1368.11 1653.54,1387.8 1653.54,1417.32 U1.19@1653.54,1419.34 1653.54,1464.62 v1(1673.23,1484.31)
  Bottom Layer w12: v1(1673.23,1514.82) 1703.74,1514.82 1707.58,1518.66 1707.58,1528.94 1711.51,1532.87 ; C28.2@1673.23,1712.6 1692.91,1712.6 1712.6,1692.91 U1.10@1712.6,1549.27 ; 1712.6,1535.43 U1.10@1712.6,1555.86
  Bottom Layer w20: C32.2@1456.69,470.47 1456.69,576.61 1637.95,757.87 U3.3@1722.44,757.87 1722.44,750 1732.28,740.16 R29.1@1868.11,740.16 2029.04,740.16 2036.91,748.03 D4.2@2104.33,748.03 ; U2.2@2744.25,695.71 U2.2@2746.06,693.9 2746.06,728.35 ; 2746.06,600.39 U2.2@2746.06,688.98
  Bottom Layer w25: 2746.06,728.35 v1(2765.75,748.03) v1(2805.12,748.03) 2805.31,747.84 2863.98,747.84 C34.2@2864.17,748.03
  Bottom Layer w50: v3@1293.87,470.47 C32.2@1456.69,470.47
  other v1: 308,66 408,66 508,66 2352.36,137.8 558,166 728.35,226.38 308,266 984.25,364.17 158,366 258,366 358,366 458,366 728.35,413.39 108,466 208,466 308,466 408,466 508,466 608,466 158,566 258,566 358,566 458,566 558,566 108,666 208,666 508,666 1062.99,728.35 158,766 258,766 358,766 458,766 558,766 1309.06,767.72 1574.8,767.72 1791.34,767.72 2411.42,767.72 2047.24,777.56 108,866 208,866 308,866 408,866 508,866 158,966 258,966 358,966 458,966 558,966 1062.99,974.41 308,1066 408,1066 508,1066 258,1166 358,1166 458,1166 558,1166 1858,1166 2058,1166 2158,1166 2258,1166 2358,1166 2458,1166 2558,1166 2658,1166 2758,1166 2858,1166 2958,1166 3058,1166 3158,1166 1908,1266 2108,1266 2208,1266 2308,1266 2408,1266 2508,1266 2608,1266 2708,1266 2808,1266 2908,1266 3008,1266 3108,1266 1062.99,1358.27 2258,1366 2358,1366 2458,1366 2558,1366 2658,1366 2758,1366 2858,1366 2958,1366 3058,1366 3158,1366 1673.23,1453.79 2208,1466 2308,1466 2408,1466 2508,1466 2608,1466 2708,1466 2808,1466 2908,1466 3008,1466 3108,1466 1642.72,1484.31 1703.74,1484.31 2258,1566 2358,1566 2458,1566 2558,1566 2658,1566 2758,1566 2858,1566 2958,1566 3058,1566 3158,1566 1208,1666 2608,1666 2708,1666 2808,1666 2908,1666 3008,1666 3108,1666 1683.07,1761.81 1158,1766 1358,1766 2558,1766 2658,1766 2758,1766 2858,1766 2958,1766 3058,1766 3158,1766 1108,1866 1208,1866 1308,1866 1408,1866 2908,1866 3008,1866 3108,1866 1258,1966 1358,1966 2558,1966 2658,1966 2758,1966 2858,1966 2958,1966 3058,1966 3158,1966 1308,2066 2608,2066 2708,2066 2808,2066 2908,2066 3008,2066 3108,2066 2558,2166 2658,2166 2758,2166 2858,2166 2958,2166 3058,2166 3158,2166 2808,2266 2908,2266 3008,2266 3108,2266 925.2,2273.62 2558,2366 2858,2366 2958,2366 3058,2366 3158,2366 2608,2466 2708,2466 2808,2466 2908,2466 2758,2566 2858,2566 2958,2566 3058,2566 3158,2566 2708,2666 2808,2666 2908,2666 3008,2666 3108,2666 2758,2766 2858,2766 2958,2766 3158,2766 925.2,3267.72 958,3366 1058,3366 1158,3366 1258,3366 1358,3366 1458,3366 1558,3366 925.2,3405.51 1008,3466 1108,3466 1208,3466 1308,3466 1408,3466 1508,3466 1608,3466 2108,3466 2208,3466 2308,3466 2408,3466 2508,3466 2608,3466 2708,3466 2808,3466 2908,3466 3008,3466 3108,3466 958,3566 1058,3566 1158,3566 1258,3566 1358,3566 1458,3566 1558,3566 2058,3566 2158,3566 2258,3566 2358,3566 2458,3566 2558,3566 2658,3566 2758,3566 2858,3566 2958,3566
  other v2: 59.33,1262.32 104.33,1262.32 149.33,1262.32 194.33,1262.32 514.33,1262.32 559.33,1262.32 59.33,1307.32 104.33,1307.32 149.33,1307.32 559.33,1307.32 59.33,1352.32 104.33,1352.32 59.33,1397.32 104.33,1397.32 59.33,1442.32 104.33,1442.32 59.33,1487.32 104.33,1487.32 59.33,1532.32 104.33,1532.32 149.33,1532.32 559.33,1532.32 59.33,1577.32 104.33,1577.32 149.33,1577.32 194.33,1577.32 514.33,1577.32 559.33,1577.32
  other v3: 797.24,147.64 2618.11,364.17 2746.06,364.17 2874.02,364.17 1289.37,472.44 2618.11,501.97 2814.96,561.02 2982.28,561.02 2814.96,866.14 2814.96,935.04 659.45,1387.8 1258,1766 1112.2,1998.03 1437.01,1998.03 1082.68,2057.09 1141.73,2057.09 1407.48,2057.09 1466.54,2057.09 1663.39,2057.09 1663.39,2273.62 1663.39,2391.73
  other v4: 925.2,2440.94 925.2,2559.06 925.2,2677.17 925.2,2805.12 925.2,2962.6 925.2,3120.08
